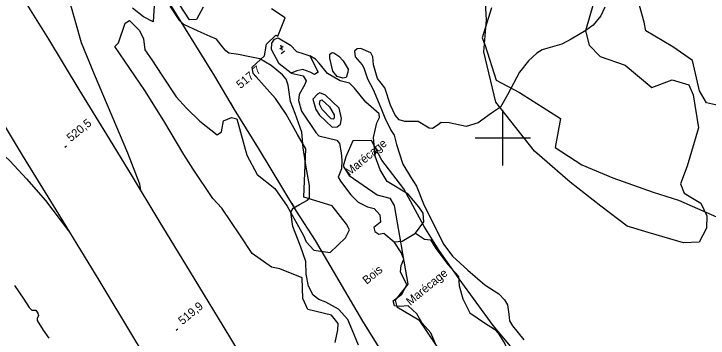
# Model space of a CAD drawing. Extents: x 347059 to 352153, y 6073752 to 6078601.
# Drawn here: x 349535.4 to 349911.2, y 6074891.7 to 6075066.9 of the extents above; entities that cross this region are included whole.
import ezdxf

# ---------------------------------------------------------------- set-up
doc = ezdxf.new("R2010")
doc.units = 0
for name, color, linetype in [('Level 1', 7, 'Continuous'), ('Level 2', 7, 'Continuous'), ('Level 25', 7, 'Continuous'), ('Level 3', 7, 'Continuous'), ('Level 37', 7, 'Continuous'), ('Level 4', 7, 'Continuous'), ('Level 44', 7, 'Continuous'), ('Level 61', 7, 'Continuous'), ('Level 7', 7, 'Continuous')]:
    doc.layers.add(name, color=color, linetype=linetype)

msp = doc.modelspace()

# ---------------------------------------------------------------- linework, layer by layer
at = {"layer": 'Level 1'}
for points in [[(349604.03, 6074971.68), (349603.49, 6074974.84), (349597.09, 6074991.67), (349588.58, 6075011.64), (349579.1, 6075034.21), (349572.04, 6075051.31), (349565.85, 6075072.85), (349558.38, 6075089.2), (349548.3, 6075106.62), (349538.13, 6075119.3), (349525.55, 6075140.33), (349515.69, 6075157.94), (349503.8, 6075177.26), (349490.58, 6075196.11), (349474.22, 6075217.44)], [(349491.15, 6075040.17), (349495.96, 6075037.32), (349500.67, 6075032.15), (349502.61, 6075027.97), (349508.83, 6075011.79), (349513.4, 6075005.61), (349522.58, 6074997.28), (349533.13, 6074987.55), (349542.24, 6074977.67), (349552.57, 6074966.12), (349565.03, 6074949.56)]]:
    msp.add_lwpolyline(points, dxfattribs=at)
at = {"layer": 'Level 2'}
for points in [[(349721.98, 6074887.82), (349718.54, 6074896.13), (349716.07, 6074901.75), (349711.08, 6074907.35), (349704.3, 6074911.15), (349700.44, 6074912.54), (349697.35, 6074914.89), (349694.86, 6074919.82), (349693.68, 6074926.24), (349693.35, 6074933.07), (349690.47, 6074941.34), (349686.4, 6074952.01), (349685.37, 6074959.68), (349686.5, 6074961.83), (349690.06, 6074963.84), (349694.34, 6074966.16), (349695.36, 6074967.54), (349695.38, 6074974.15), (349693.65, 6074984.09), (349691.93, 6074994.57), (349691.22, 6075003.05), (349687.58, 6075013.14), (349685.13, 6075019.49), (349683.88, 6075028.43), (349682.69, 6075031.57), (349680.85, 6075033.94), (349674.57, 6075039.03), (349668.6, 6075042.59), (349661.25, 6075044.01), (349656.92, 6075044.97), (349651.68, 6075045.75), (349650.2, 6075046.99), (349648.38, 6075049.16), (349644.98, 6075053.23), (349641.68, 6075054.66), (349635.06, 6075057.54), (349627.41, 6075061.21), (349625.22, 6075063.2), (349620.06, 6075071.08)], [(349855.29, 6075070.48), (349853.05, 6075065.94), (349849.03, 6075060.79)], [(349849.03, 6075060.79), (349844.9, 6075057.97), (349837.03, 6075053.24), (349832.02, 6075050.47), (349824.48, 6075048.46), (349821.39, 6075047.51), (349818.39, 6075045.7), (349813.94, 6075041.52), (349809.16, 6075035.37), (349802.5, 6075023.11), (349798.77, 6075016.54), (349793.91, 6075013.29), (349786.67, 6075008.04), (349780.18, 6075006.04), (349770.98, 6075007.99), (349766.76, 6075008.19), (349765.02, 6075006.88), (349762.04, 6075005.05), (349760.1, 6075005.22), (349754.18, 6075008.73), (349747.01, 6075008.7), (349743.92, 6075009.71), (349741.86, 6075012.18), (349739.21, 6075017.6), (349736.18, 6075026.99), (349732.18, 6075032.04), (349730.1, 6075039.3), (349729.65, 6075043.8), (349728.53, 6075045.87), (349723.27, 6075048.21), (349721.3, 6075048.06), (349719.71, 6075046.73), (349720.14, 6075043.78), (349723.95, 6075039.39), (349724.9, 6075037.71), (349726.74, 6075031.82), (349729.89, 6075026.07), (349734.07, 6075016.21), (349736.18, 6075010.72), (349739.51, 6075004.13), (349741.21, 6075001.29), (349742.42, 6074996.24), (349745.88, 6074985.73), (349750.06, 6074978.75), (349753.31, 6074973.77), (349757.18, 6074964.3), (349763.85, 6074950.68), (349768.21, 6074942.23), (349772.84, 6074935.96), (349781.06, 6074928.37), (349790.3, 6074920.44), (349797.82, 6074915.58), (349801, 6074912.4), (349802.55, 6074909.69), (349803.3, 6074904.65), (349803.72, 6074901.08), (349805.33, 6074898.3), (349811.46, 6074890.66)], [(349713.72, 6075041.52), (349716.34, 6075037.12), (349716.24, 6075035.45), (349715.33, 6075032.58), (349713.42, 6075032.18), (349710.31, 6075033.03), (349708, 6075035.97), (349706.38, 6075042.95), (349706.48, 6075045.07), (349707.63, 6075046.03), (349708.55, 6075045.83), (349711.33, 6075044.03), (349713.72, 6075041.52)], [(349707.2, 6075010.11), (349702.23, 6075015.17), (349700.86, 6075018.15), (349701.2, 6075020.08), (349702.17, 6075020.53), (349706.2, 6075016.7), (349708.79, 6075012.42), (349708.79, 6075010.54), (349708.16, 6075009.94), (349707.2, 6075010.11)], [(349535.73, 6074920.04), (349540.8, 6074912.75), (349543.61, 6074908.14), (349545.05, 6074906.81), (349547.21, 6074906.67)], [(349547.21, 6074906.67), (349548.35, 6074905.22), (349548.7, 6074903.89), (349548.02, 6074902.34), (349548.01, 6074901.11), (349551.3, 6074895.96), (349554.27, 6074891.63)]]:
    msp.add_lwpolyline(points, dxfattribs=at)
at = {"layer": 'Level 25'}
for points in [[(349784.38, 6074675.53), (349768.37, 6074701.83), (349743.34, 6074742.62), (349721.53, 6074778.43), (349696.21, 6074820.32), (349678.53, 6074848.95), (349661.66, 6074876.79), (349648.66, 6074898.31), (349631.08, 6074927.35), (349614, 6074955), (349599.14, 6074979.85), (349585.75, 6075001.78), (349570.8, 6075026.04), (349554.23, 6075053.21), (349538.16, 6075079.35)], [(349520.07, 6075023.29), (349539.95, 6074990.52), (349559.48, 6074958.63), (349581.29, 6074923), (349600.2, 6074891.88), (349620.41, 6074858.47), (349638.31, 6074829.23), (349656.2, 6074799.57), (349678.59, 6074762.81), (349696.19, 6074734.05), (349714.33, 6074704.28), (349729.9, 6074678.44), (349746.4, 6074651.32), (349749.31, 6074646.55)]]:
    msp.add_lwpolyline(points, dxfattribs=at)
at = {"layer": 'Level 3'}
for p, q in [((349679.34, 6075047.99), (349681.15, 6075049.48)), ((349679.8, 6075050.12), (349680.63, 6075047.37)), ((349680.06, 6075045.47), (349681.91, 6075047)), ((349562.91, 6074994.84), (349563.83, 6074995.61)), ((349623.29, 6074895.89), (349624.21, 6074896.66))]:
    msp.add_line(p, q, dxfattribs=at)
at = {"layer": 'Level 37'}
for points in [[(349831.31, 6074714.31), (349812.61, 6074745.27), (349809.11, 6074751.23), (349749.75, 6074859.9), (349724.27, 6074900.83), (349698.65, 6074944.47), (349688.46, 6074960.35), (349667.84, 6074994.28), (349654.77, 6075015.26), (349644.24, 6075033.23), (349636.23, 6075046.12), (349615.69, 6075079.37), (349598.23, 6075108.69), (349592.96, 6075105.91), (349580.98, 6075125.99), (349566.24, 6075149.37), (349547.65, 6075180.79), (349528.46, 6075211.86), (349509.81, 6075242.39), (349492.18, 6075271.71), (349497.22, 6075274.53), (349477.61, 6075308.05), (349471.31, 6075319.03), (349431.44, 6075385.01)], [(349639.25, 6075041.26), (349636.23, 6075046.12), (349636.08, 6075046.35)], [(349644.52, 6075032.76), (349644.24, 6075033.23), (349641.36, 6075037.86)], [(349655.68, 6075013.8), (349654.77, 6075015.26), (349652.61, 6075018.95)], [(349669.4, 6074991.71), (349667.84, 6074994.28), (349666.26, 6074996.82)], [(349689.16, 6074959.25), (349688.46, 6074960.35), (349686.02, 6074964.37)], [(349727.35, 6074895.89), (349724.27, 6074900.83), (349724.19, 6074900.98)]]:
    msp.add_lwpolyline(points, dxfattribs=at)
at = {"layer": 'Level 4'}
msp.add_lwpolyline([(349685.44, 6075034.93), (349679.06, 6075039.97), (349674.89, 6075047.61), (349675.05, 6075051.07), (349676.48, 6075053.33), (349678.5, 6075053.97), (349685.14, 6075050.06), (349688.41, 6075046.63), (349691.81, 6075045.57), (349695.59, 6075044.25), (349700.07, 6075035.5), (349698.06, 6075034.12), (349695.82, 6075035.4), (349691.89, 6075036.91), (349688.55, 6075036.06), (349685.44, 6075034.93)], dxfattribs=at)
at = {"layer": 'Level 44'}
for points in [[(349916.72, 6075017.36), (349910.27, 6075018.83), (349906.49, 6075025.37), (349902.65, 6075041.72), (349892.12, 6075049.18), (349877.38, 6075057.76), (349876.51, 6075062.42), (349870.97, 6075082.63), (349859.92, 6075120.91), (349847.42, 6075130.39), (349842.73, 6075138.03), (349826.67, 6075153.44), (349819.33, 6075167.01)], [(349637.82, 6075070.65), (349634.2, 6075063.84), (349630.51, 6075063.75), (349622.28, 6075076.29)], [(349611.36, 6075071.38), (349610.76, 6075062.58), (349605.52, 6075065.26), (349599.65, 6075070.11)], [(349645.52, 6075001.53), (349647.7, 6075003.22), (349648.88, 6075009.16), (349653.27, 6075010.9), (349656.07, 6075010.24), (349661.5, 6074990.5), (349667.03, 6074980.14), (349676.63, 6074972.61), (349683.28, 6074963.06), (349692.2, 6074947.04), (349693.62, 6074943.74), (349697.77, 6074939.14), (349706.54, 6074937.97), (349714.97, 6074945.79), (349716.99, 6074950.18), (349715.4, 6074953.33), (349707.64, 6074963.14), (349692.26, 6074967.91), (349693.43, 6074993.93), (349688.99, 6075001.75), (349682.7, 6075012.68), (349677.01, 6075021.27), (349664.99, 6075034.76), (349664.39, 6075038.16), (349671.13, 6075044.28), (349672.09, 6075050.5), (349677.17, 6075055.38), (349678.28, 6075054.95), (349682.25, 6075064.76), (349674.91, 6075069.59)], [(349793.97, 6075070.24), (349788.91, 6075053.99), (349790.5, 6075049.92), (349796.53, 6075031.15), (349809.03, 6075024.4), (349831.28, 6075010.44), (349828.37, 6074994.7), (349842.88, 6074985.36), (349859.62, 6074978.35), (349881.4, 6074970.49), (349895.22, 6074966.27), (349915.79, 6074957.14)], [(349709.28, 6074889.35), (349710.69, 6074896.06), (349711.01, 6074899.6), (349707.33, 6074903.99), (349694.52, 6074907.13), (349691.72, 6074913.15), (349691.48, 6074924.15), (349679.3, 6074929.04), (349674.91, 6074929.99), (349664.34, 6074937.42), (349657.66, 6074947.53), (349647.92, 6074961.83), (349643.08, 6074967.06), (349632.49, 6074982.92), (349627.31, 6074990.88), (349616.51, 6075009.13), (349606.35, 6075025.55), (349590.11, 6075049.23), (349592, 6075051.27), (349595.7, 6075061.91), (349597.94, 6075063.35), (349603.36, 6075057.96), (349605.5, 6075053.44), (349606.28, 6075047.48), (349609.99, 6075042.16), (349615.54, 6075033.74), (349623.25, 6075022.03), (349628.92, 6075015.97), (349635.98, 6075008.98), (349645.52, 6075001.53)], [(349808.9, 6074881.7), (349794.84, 6074898.52), (349776.49, 6074923.7), (349765.51, 6074938.99), (349757.4, 6074951.92), (349746.56, 6074972.43), (349734.59, 6074987.84), (349729.02, 6074998.45), (349718.82, 6074998.28), (349715.11, 6074989.62), (349713.68, 6074984.52), (349716.82, 6074979.51), (349732.1, 6074969.12), (349738.94, 6074967.38), (349741.27, 6074963.34), (349748.67, 6074920.83), (349741.87, 6074912.14), (349742.77, 6074908.57), (349754.58, 6074901.6), (349768.4, 6074880.98)]]:
    msp.add_lwpolyline(points, dxfattribs=at)
at = {"layer": 'Level 61'}
for p, q in [((349800, 6074985), (349800, 6075015)), ((349785, 6075000), (349815, 6075000))]:
    msp.add_line(p, q, dxfattribs=at)
at = {"layer": 'Level 7'}
for points in [[(349849.12, 6075072.79), (349844.81, 6075057.77), (349846.71, 6075050.07), (349852.66, 6075043.98), (349866.23, 6075039.18), (349880.74, 6075027.11), (349891.7, 6075031.21), (349900.74, 6075028.62), (349903.16, 6075023.18), (349906.04, 6075005.28), (349899.88, 6074984.6), (349896.22, 6074974.98), (349898.2, 6074970.08), (349907.27, 6074964.56), (349910.53, 6074957.76), (349910.39, 6074951.1), (349906.27, 6074943.48), (349897.8, 6074943.24), (349878.66, 6074948.66), (349867.45, 6074952.08), (349853.02, 6074962.95), (349836.5, 6074975.97), (349817.21, 6074992.67), (349796.35, 6075019.16), (349789.86, 6075046.4), (349791.27, 6075063.8), (349789.37, 6075094.97)], [(349849.12, 6075072.79), (349844.81, 6075057.77), (349846.71, 6075050.07), (349852.66, 6075043.98), (349866.23, 6075039.18), (349880.74, 6075027.11), (349891.7, 6075031.21), (349900.74, 6075028.62), (349903.16, 6075023.18), (349906.04, 6075005.28), (349899.88, 6074984.6), (349896.22, 6074974.98), (349898.2, 6074970.08), (349907.27, 6074964.56), (349910.53, 6074957.76), (349910.39, 6074951.1), (349906.27, 6074943.48), (349897.8, 6074943.24), (349878.66, 6074948.66), (349867.45, 6074952.08), (349853.02, 6074962.95), (349836.5, 6074975.97), (349817.21, 6074992.67), (349796.35, 6075019.16), (349789.86, 6075046.4), (349791.27, 6075063.8), (349789.37, 6075094.97)], [(349685.44, 6075034.93), (349692.06, 6075033.42), (349693.6, 6075030.81), (349692.92, 6075028.72), (349689.89, 6075023.31), (349689.51, 6075020.13), (349691.08, 6075014.38), (349698.88, 6075002.87), (349700.41, 6075001), (349710.28, 6074998.61), (349711.58, 6074996.85), (349712.49, 6074991.74), (349712.94, 6074987.91), (349712.65, 6074983.16), (349711, 6074978.61), (349712.27, 6074976.52), (349717.85, 6074969.18), (349721.77, 6074965.12), (349726.75, 6074962.69), (349730.49, 6074961.77), (349733.41, 6074958.22), (349733.93, 6074954.3), (349730.32, 6074951.42), (349730.7, 6074949.33), (349732.99, 6074947.8), (349735.72, 6074948.3), (349741.3, 6074943.68), (349745.64, 6074944.02), (349752.81, 6074948.39), (349757.37, 6074954.48), (349757, 6074959.12), (349754.64, 6074962.55), (349748.79, 6074969.5), (349737.48, 6074976.37), (349733.68, 6074982.65), (349730.96, 6074989.98), (349730.12, 6075000.11), (349731.94, 6075008.1), (349733.35, 6075010.94), (349733.12, 6075012.86), (349725.91, 6075019.29), (349719.85, 6075026.69), (349717.01, 6075029.42), (349711.92, 6075030.71), (349705.21, 6075034.7), (349700.68, 6075040.23), (349698.69, 6075042.48), (349695.59, 6075044.25)], [(349700.9, 6075012.25), (349707.69, 6075005.61), (349710.39, 6075005.78), (349712.16, 6075007.26), (349712.77, 6075010.34), (349711.43, 6075015.99), (349704.03, 6075023.01), (349701.05, 6075024.27), (349699.76, 6075023.48), (349697.15, 6075020.83), (349698.83, 6075015.32), (349700.9, 6075012.25)], [(349752.81, 6074948.39), (349757.64, 6074945.12), (349760.87, 6074944.84), (349763.85, 6074940.02), (349770.55, 6074931.29), (349776.01, 6074925.11), (349776.5, 6074919.86), (349778.4, 6074912.94), (349782.18, 6074905.37), (349790.14, 6074899.96), (349795.59, 6074896.48), (349797.51, 6074894.36), (349801.2, 6074888.52), (349804.19, 6074881.19), (349801.53, 6074877.93), (349800.15, 6074872.6), (349802.66, 6074868), (349812.02, 6074857.7), (349816.53, 6074852.85), (349819.83, 6074847.29), (349819.49, 6074845.37), (349816.5, 6074842.92)], [(349801.14, 6074841.84), (349795.23, 6074847.29), (349789.74, 6074848.5), (349785.49, 6074853.57), (349781.28, 6074860.75), (349778.17, 6074868.57), (349774.2, 6074878.5), (349767.38, 6074882.18), (349764.73, 6074886.07), (349761.01, 6074894.44), (349756.37, 6074899.8), (349753.5, 6074904.85), (349748.84, 6074909.16), (349744.32, 6074908.66), (349741.43, 6074909.07), (349740.7, 6074911.74), (349745.33, 6074915.33), (349748.16, 6074920.53), (349744.63, 6074927.44), (349745.03, 6074930.9), (349746.55, 6074934.27), (349745, 6074937.91), (349741.3, 6074943.68)]]:
    msp.add_lwpolyline(points, dxfattribs=at)

# ---------------------------------------------------------------- texts
at = {"layer": 'Level 3'}
for s, rotation, p in [('  517,7', 39.57, (349655.48, 6075024.13)), ('520,5', 39.62, (349566.27, 6074997.56)), ('519,9', 39.62, (349626.65, 6074898.6))]:
    msp.add_text(s, height=4.5, rotation=rotation, dxfattribs=at).set_placement(p)
at = {"layer": 'Level 44'}
msp.add_text('Bois', height=4.5, rotation=39.568, dxfattribs=at).set_placement((349726.38, 6074920.46))
at = {"layer": 'Level 7'}
for p in [(349717.08, 6074979.21), (349749.98, 6074909.04)]:
    msp.add_text('Marécage', height=4.5, rotation=39.568, dxfattribs=at).set_placement(p)

doc.saveas('drawing.dxf')
